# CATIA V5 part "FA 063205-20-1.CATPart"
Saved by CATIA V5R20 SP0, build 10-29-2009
Part number: FA 063205-20-1
Revision: ANY
Definition: UNKNOWN
Nomenclature: FA 063205-20-1
Source: Unknown
Bounding box of the stored display mesh (mm): x -3 to 3, y -9.95 to 10.05, z -3 to 3
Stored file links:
  C:\Users\Utente\Desktop\IO LAVORO\3D X SITO CF\CUMSA\3D files FA\FA 063205-20\FA 063205-20-1.CATPart

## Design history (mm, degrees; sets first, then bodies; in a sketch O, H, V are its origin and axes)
Body1 "Cortar-Extruir5" (main body)
  Solid1: solid without history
